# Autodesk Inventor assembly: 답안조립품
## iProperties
Created: 2014-12
Part Number: 답안조립품
Document SubType Name: Assembly
Designer: elite
Mass: 6468.99 g
Surface Area: 4235.08 cm^2
Volume: 1870.37 cm^3
Density: 3.45867 g/cm^3
Author: elite
